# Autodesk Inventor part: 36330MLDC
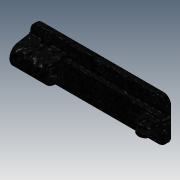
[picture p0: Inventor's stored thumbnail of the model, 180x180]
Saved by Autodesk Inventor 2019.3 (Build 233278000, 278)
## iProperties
Created: 2012-06
Part Number: 36330MLDC
Material: Ogólny
Document SubType Name: Modeling
Designer: CADENGINEERING4
Density: 1 g/cm^3
Appearance: Czarny
Author: CADENGINEERING4
Revision Number: 1LAST_VERSION
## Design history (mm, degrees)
feature "Baza1"
node "Bryła1"
